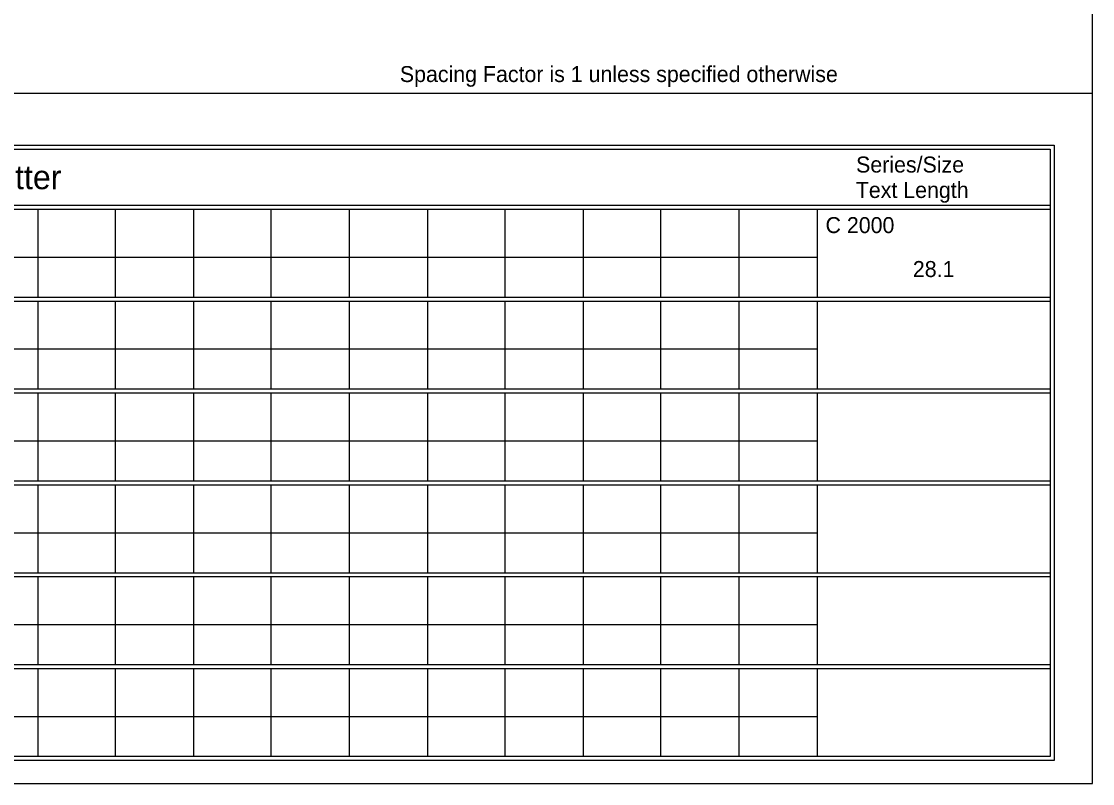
# Model space of a CAD drawing. Extents: x 57.2 to 85.4, y 153.3 to 173.4.
# Drawn here: x 63.11 to 69.71, y 163.71 to 168.41 of the extents above; entities that cross this region are included whole.
import ezdxf

# ---------------------------------------------------------------- set-up
doc = ezdxf.new("R2010")
doc.units = 0
doc.layers.add('Default', color=7, linetype='Continuous')

msp = doc.modelspace()

# ---------------------------------------------------------------- linework, layer by layer
at = {"layer": 'Default'}
for p, q in [((69.7108, 163.7124), (69.7108, 173.0983)), ((57.2061, 167.9646), (69.7108, 167.9646)), ((57.4225, 167.6428), (69.4747, 167.6428)), ((69.4747, 167.6428), (69.4747, 163.855)), ((57.4471, 167.6182), (69.4501, 167.6182)), ((69.4501, 167.6182), (69.4501, 163.8796)), ((57.4471, 167.2739), (69.4501, 167.2739)), ((57.4471, 167.2493), (69.4501, 167.2493)), ((63.2125, 167.2493), (63.2125, 166.7082)), ((63.6897, 167.2493), (63.6897, 166.7082)), ((64.1718, 167.2493), (64.1718, 166.7082)), ((64.6489, 167.2493), (64.6489, 166.7082)), ((65.131, 167.2493), (65.131, 166.7082)), ((65.6131, 167.2493), (65.6131, 166.7082)), ((66.0903, 167.2493), (66.0903, 166.7082)), ((66.5724, 167.2493), (66.5724, 166.7082)), ((67.0495, 167.2493), (67.0495, 166.7082)), ((67.5316, 167.2493), (67.5316, 166.7082)), ((68.0137, 167.2493), (68.0137, 166.7082)), ((57.4471, 166.9541), (68.0137, 166.9541)), ((57.4471, 166.7082), (69.4501, 166.7082)), ((57.4471, 166.6836), (69.4501, 166.6836)), ((63.2125, 166.6836), (63.2125, 166.1425)), ((63.6897, 166.6836), (63.6897, 166.1425)), ((64.1718, 166.6836), (64.1718, 166.1425)), ((64.6489, 166.6836), (64.6489, 166.1425)), ((65.131, 166.6836), (65.131, 166.1425)), ((65.6131, 166.6836), (65.6131, 166.1425)), ((66.0903, 166.6836), (66.0903, 166.1425)), ((66.5724, 166.6836), (66.5724, 166.1425)), ((67.0495, 166.6836), (67.0495, 166.1425)), ((67.5316, 166.6836), (67.5316, 166.1425)), ((68.0137, 166.6836), (68.0137, 166.1425)), ((57.4471, 166.3884), (68.0137, 166.3884)), ((57.4471, 166.1425), (69.4501, 166.1425)), ((57.4471, 166.1179), (69.4501, 166.1179)), ((63.2125, 166.1179), (63.2125, 165.5768)), ((63.6897, 166.1179), (63.6897, 165.5768)), ((64.1718, 166.1179), (64.1718, 165.5768)), ((64.6489, 166.1179), (64.6489, 165.5768)), ((65.131, 166.1179), (65.131, 165.5768)), ((65.6131, 166.1179), (65.6131, 165.5768)), ((66.0903, 166.1179), (66.0903, 165.5768)), ((66.5724, 166.1179), (66.5724, 165.5768)), ((67.0495, 166.1179), (67.0495, 165.5768)), ((67.5316, 166.1179), (67.5316, 165.5768)), ((68.0137, 166.1179), (68.0137, 165.5768)), ((57.4471, 165.8227), (68.0137, 165.8227)), ((57.4471, 165.5768), (69.4501, 165.5768)), ((57.4471, 165.5522), (69.4501, 165.5522)), ((63.2125, 165.5522), (63.2125, 165.011)), ((63.6897, 165.5522), (63.6897, 165.011)), ((64.1718, 165.5522), (64.1718, 165.011)), ((64.6489, 165.5522), (64.6489, 165.011)), ((65.131, 165.5522), (65.131, 165.011)), ((65.6131, 165.5522), (65.6131, 165.011)), ((66.0903, 165.5522), (66.0903, 165.011)), ((66.5724, 165.5522), (66.5724, 165.011)), ((67.0495, 165.5522), (67.0495, 165.011)), ((67.5316, 165.5522), (67.5316, 165.011)), ((68.0137, 165.5522), (68.0137, 165.011)), ((57.4471, 165.257), (68.0137, 165.257)), ((57.4471, 165.011), (69.4501, 165.011)), ((57.4471, 164.9864), (69.4501, 164.9864)), ((63.2125, 164.9864), (63.2125, 164.4453)), ((63.2125, 164.9864), (63.2125, 164.4453)), ((63.6897, 164.9864), (63.6897, 164.4453)), ((63.6897, 164.9864), (63.6897, 164.4453)), ((64.1718, 164.9864), (64.1718, 164.4453)), ((64.1718, 164.9864), (64.1718, 164.4453)), ((64.6489, 164.9864), (64.6489, 164.4453)), ((64.6489, 164.9864), (64.6489, 164.4453)), ((65.131, 164.9864), (65.131, 164.4453)), ((65.131, 164.9864), (65.131, 164.4453)), ((65.6131, 164.9864), (65.6131, 164.4453)), ((65.6131, 164.9864), (65.6131, 164.4453)), ((66.0903, 164.9864), (66.0903, 164.4453)), ((66.0903, 164.9864), (66.0903, 164.4453)), ((66.5724, 164.9864), (66.5724, 164.4453)), ((66.5724, 164.9864), (66.5724, 164.4453)), ((67.0495, 164.9864), (67.0495, 164.4453)), ((67.0495, 164.9864), (67.0495, 164.4453)), ((67.5316, 164.9864), (67.5316, 164.4453)), ((67.5316, 164.9864), (67.5316, 164.4453)), ((68.0137, 164.9864), (68.0137, 164.4453)), ((68.0137, 164.9864), (68.0137, 164.4453)), ((57.4471, 164.6913), (68.0137, 164.6913)), ((57.4471, 164.4453), (69.4501, 164.4453)), ((57.4471, 164.4207), (69.4501, 164.4207)), ((63.2125, 164.4207), (63.2125, 163.8796)), ((63.6897, 164.4207), (63.6897, 163.8796)), ((64.1718, 164.4207), (64.1718, 163.8796)), ((64.6489, 164.4207), (64.6489, 163.8796)), ((65.131, 164.4207), (65.131, 163.8796)), ((65.6131, 164.4207), (65.6131, 163.8796)), ((66.0903, 164.4207), (66.0903, 163.8796)), ((66.5724, 164.4207), (66.5724, 163.8796)), ((67.0495, 164.4207), (67.0495, 163.8796)), ((67.5316, 164.4207), (67.5316, 163.8796)), ((68.0137, 164.4207), (68.0137, 163.8796)), ((57.4471, 164.1256), (68.0137, 164.1256)), ((57.4471, 164.1256), (68.0137, 164.1256)), ((69.4501, 163.8796), (57.4471, 163.8796)), ((69.4747, 163.855), (57.4225, 163.855)), ((57.2061, 163.7124), (69.7108, 163.7124))]:
    msp.add_line(p, q, dxfattribs=at)

# ---------------------------------------------------------------- texts
for s, height, p in [('Spacing Factor is 1 unless specified otherwise', 0.098375, (65.4432, 168.0321)), ('Series/Size', 0.098385, (68.2539, 167.4749)), ('Letter spacings are to start of next letter', 0.147548, (59.8813, 167.3723)), ('Text Length', 0.098385, (68.2522, 167.3182)), ('C 2000', 0.09837, (68.0657, 167.1021)), ('28.1', 0.09837, (68.6037, 166.8315))]:
    msp.add_text(s, height=height, dxfattribs=at).set_placement(p)

doc.saveas('drawing.dxf')
